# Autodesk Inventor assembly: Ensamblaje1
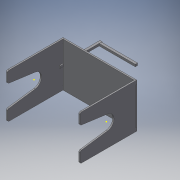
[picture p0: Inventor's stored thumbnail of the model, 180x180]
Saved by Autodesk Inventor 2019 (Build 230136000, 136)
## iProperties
Created: 2019-02
Part Number: Ensamblaje1
Material: Genérico
Document SubType Name: Assembly
Designer: Juan Manuel Montalvo Navarrete
Author: Juan Manuel Montalvo Navarrete
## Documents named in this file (6)
- C:\Users\jmontalvon\Downloads\Assignments Jorge\Table Assembly.iam
- C:\Users\jmontalvon\Downloads\Assignments Jorge\Support1.ipt
- C:\Users\jmontalvon\Downloads\Assignments Jorge\Support2.ipt
- C:\Users\jmontalvon\Downloads\Assignments Jorge\Right.ipt
- C:\Users\jmontalvon\Downloads\Assignments Jorge\Left.ipt
- C:\Users\jmontalvon\Downloads\Assignments Jorge\Table1.ipt
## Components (5 placed, 5 different names)
1. Support1:1 — Mate:3, Mate:4, Mate:5, Flush:5, Mate:6, Mate:7
2. Support2:1 — Flush:5, Mate:6, Mate:7
3. Right:1 — Coincidencia:2, Nivelación:2, Nivelación:3
4. Left:1 — Coincidencia:1, Nivelación:1, Nivelación:4, Mate:4, Mate:5
5. Table1:1 — Coincidencia:1, Nivelación:1, Coincidencia:2, Nivelación:2, Nivelación:3, Nivelación:4, Mate:3
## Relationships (12: Mate 7, Flush 5)
- Coincidencia:1 [Mate]: Left:1 ↔ Table1:1
- Nivelación:1 [Flush]: Left:1 ↔ Table1:1
- Coincidencia:2 [Mate]: Right:1 ↔ Table1:1
- Nivelación:2 [Flush]: Right:1 ↔ Table1:1
- Nivelación:3 [Flush]: Right:1 ↔ Table1:1
- Nivelación:4 [Flush]: Left:1 ↔ Table1:1
- Mate:3: Support1:1 ↔ Table1:1
- Mate:4: Support1:1 ↔ Left:1
- Mate:5: Support1:1 ↔ Left:1
- Flush:5: Support1:1 ↔ Support2:1
- Mate:6: Support1:1 ↔ Support2:1
- Mate:7: Support1:1 ↔ Support2:1
